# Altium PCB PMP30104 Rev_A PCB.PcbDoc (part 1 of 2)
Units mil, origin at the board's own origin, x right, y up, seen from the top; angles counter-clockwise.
Board outline 1835 x 2150 mil, 2 copper layers (Top Layer, Bottom Layer), stack 62 mil thick; 81 components, 42 nets, 182 pads, 76 vias.
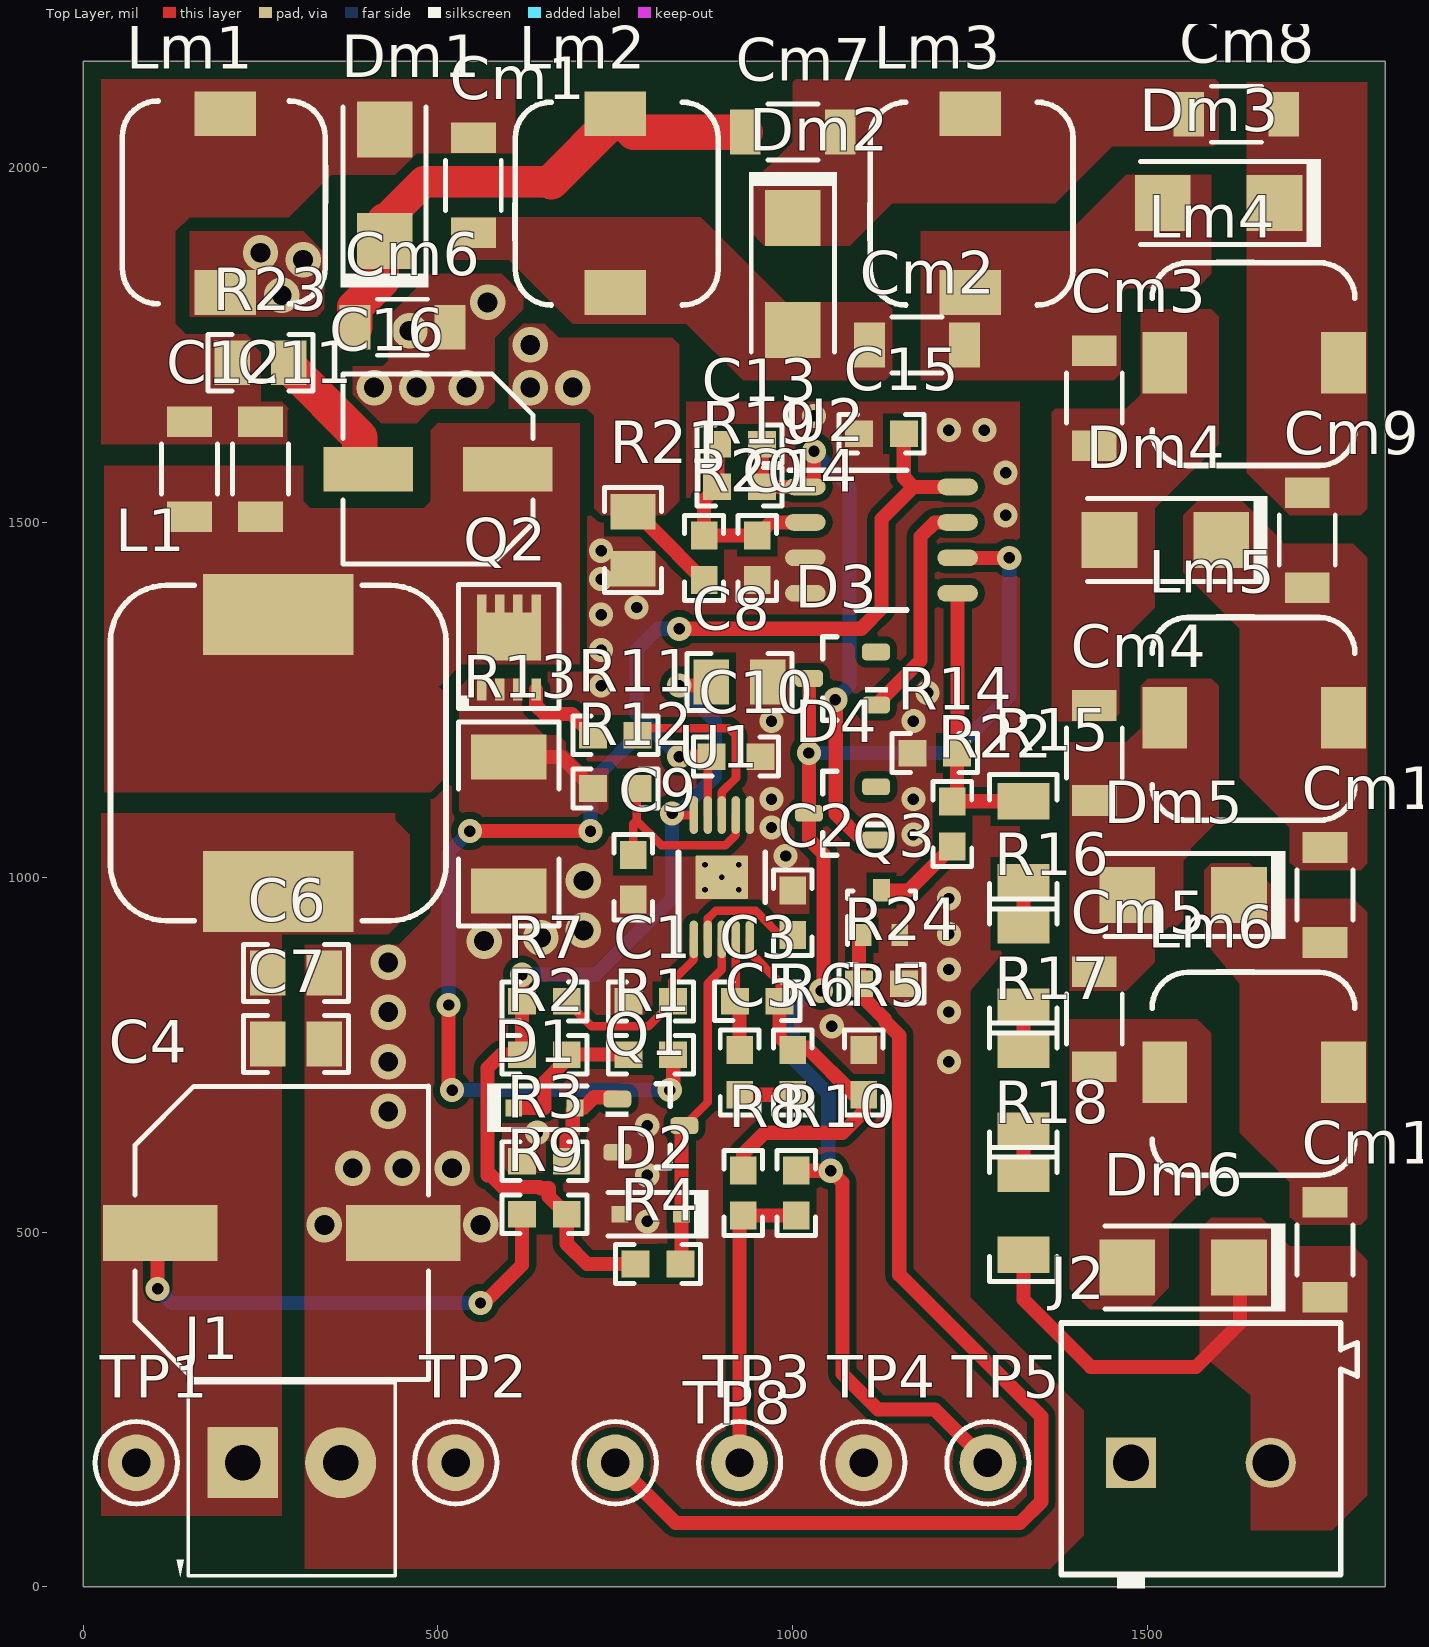
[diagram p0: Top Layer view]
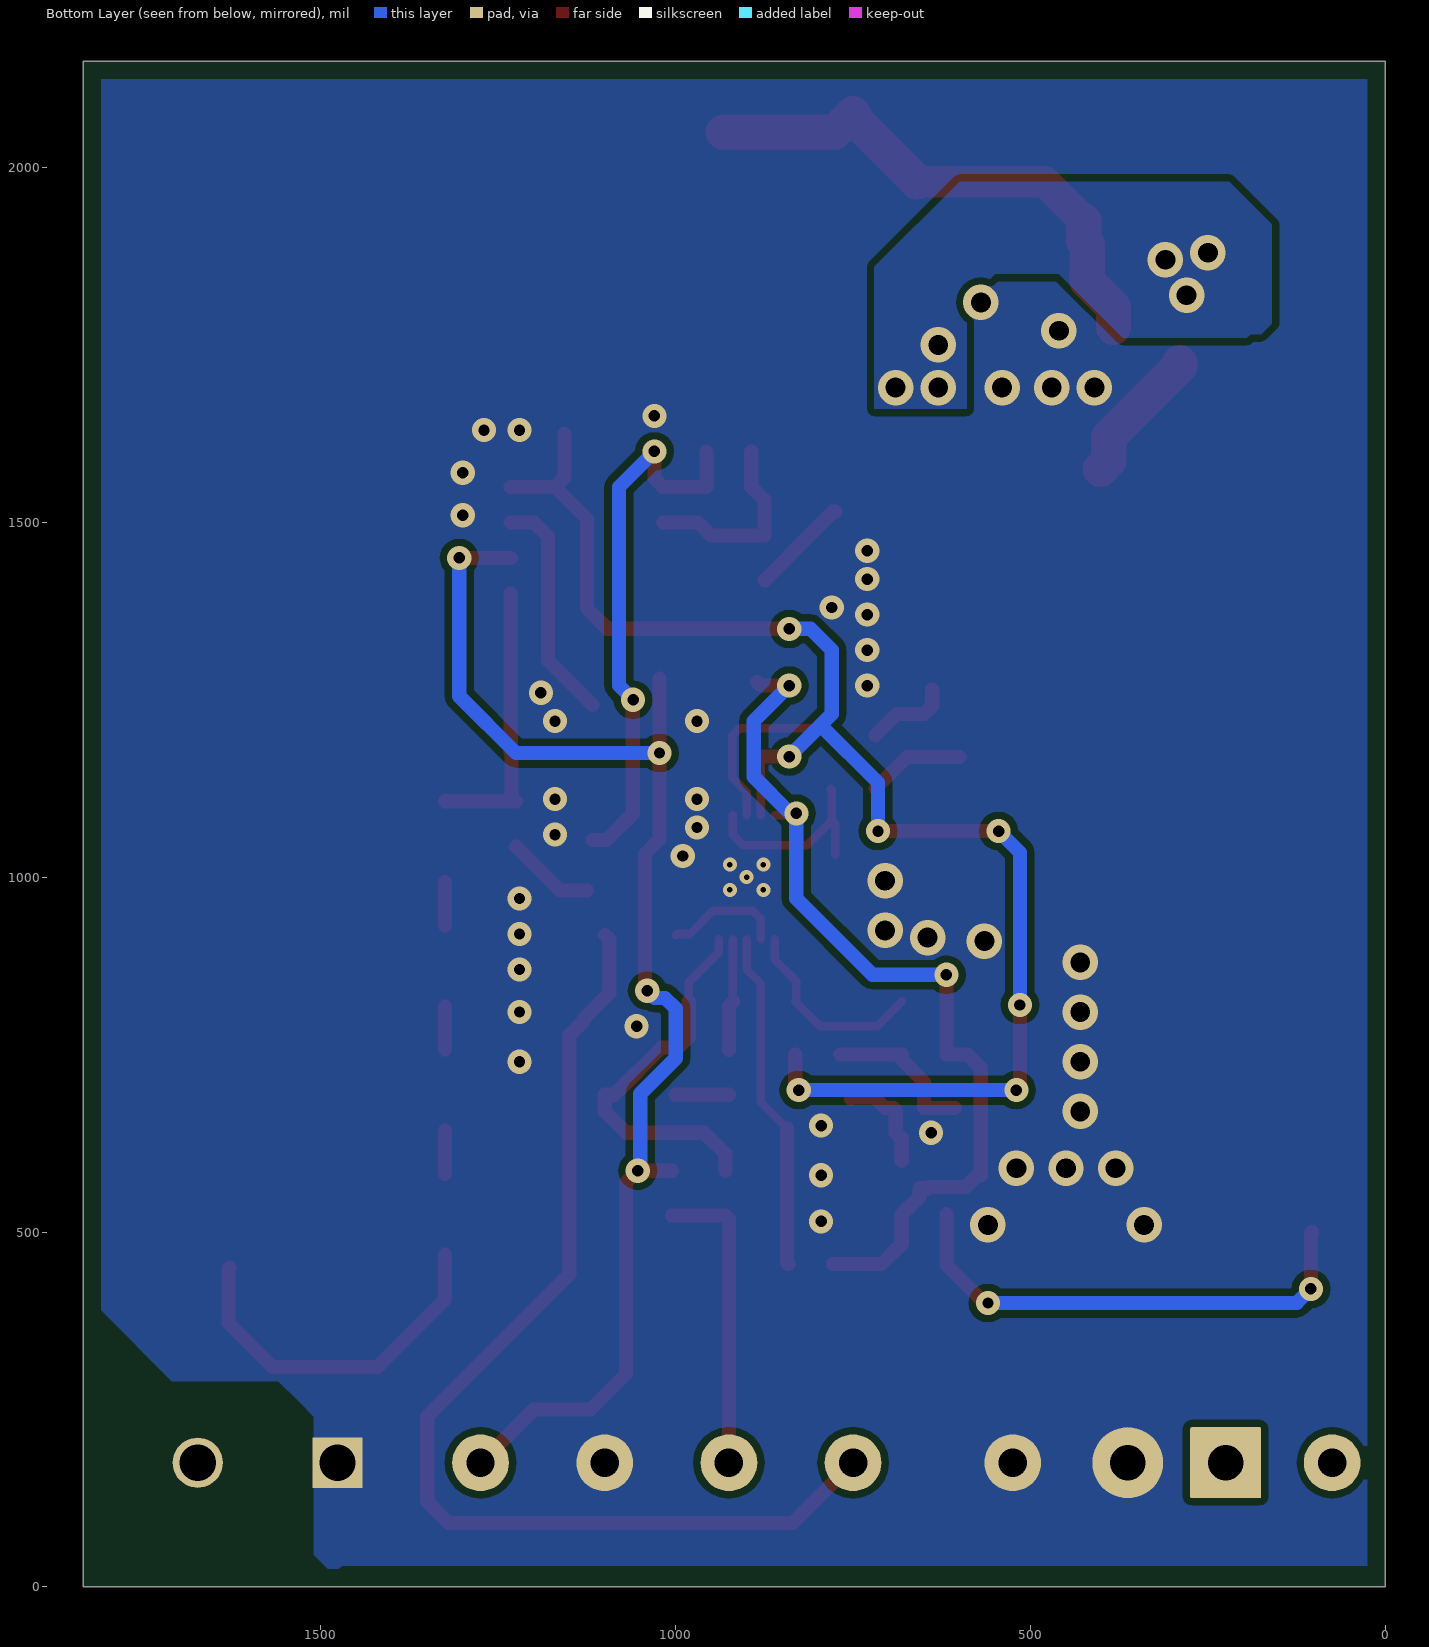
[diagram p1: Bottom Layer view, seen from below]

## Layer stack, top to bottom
Top Solder: solder mask 0.4, Solder Resist, Dk 3.5
Top Layer: signal copper 1.4
Dielectric1: core 59.2, FR-4, Dk 4.8
Bottom Layer: signal copper 1.4
Bottom Solder: solder mask 0.4, Solder Resist, Dk 3.5

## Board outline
0,0 0,2150 1835,2150 1835,0

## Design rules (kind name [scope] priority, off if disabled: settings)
AcuteAngle [All] p1: minimum=4.50000000000000E+0001 checktracksonly=FALSE
AssemblyTestPointUsage [All] p1: valid=2
BoardOutlineClearance BoardOutlineClearance_MountingHoles [OnCopper and InComponentClass('Mounting Holes')] p1: gap=40
BoardOutlineClearance BoardOutlineClearance_Poly [OnCopper and IsPoly] p2: gap=25
BoardOutlineClearance [OnCopper and Not InComponentClass('Logo') and not InComponentClass('FiducialMark') and not InRegion(1000,500,4000,800) and not InPoly] p3: gap=75
Clearance Clearance_Keepouts [((IsTrack Or IsArc) And Not InPoly) And IsFree and IsKeepOut vs ((IsTrack Or IsArc) And Not InPoly) And IsFree and IsKeepOut] p1: gap=0
Clearance Clearance_Poly [InPolygon] p2: gap=10
Clearance [All] p3: gap=8
ComponentClearance ComponentClearance_MountingHoles_FiducialMarks [InComponentClass('Mounting Holes') vs InComponentClass('FiducialMark')] p1: gap=50 collisioncheckmode=3 verticalgap=10 showdistances=FALSE
ComponentClearance ComponentClearance_Shunt [InComponentClass('Header') vs InComponentClass('Shunt')] p2: gap=0 collisioncheckmode=3 verticalgap=0 showdistances=FALSE
ComponentClearance ComponentClearance_Logo [InComponentClass('Logo')] p3: gap=50 collisioncheckmode=3 verticalgap=10 showdistances=FALSE
ComponentClearance ComponentClearance_ScrewToNut [(HasFootprint('NY PMS 440 0025 PH')) vs (HasFootprint('Keystone_1902C'))] p4: gap=5 collisioncheckmode=3 verticalgap=10 showdistances=FALSE
ComponentClearance ComponentClearance_MountingHoles [InComponentClass('Mounting Holes')] p5: gap=250 collisioncheckmode=3 verticalgap=100000 showdistances=FALSE
ComponentClearance ComponentClearance_SmallPassives [HasFootprint('0201*') or HasFootprint('0402*') or HasFootprint('0508') or HasFootprint('0603*') or HasFootprint('0612') or HasFootprint('0805*') or HasFootprint('0815*') or HasFootprint('0830*') or HasFootprint('1206*') or HasFootprint('1210*') or HasFootprint('1808*') or HasFootprint('1812*') or HasFootprint('1825*') or HasFootprint('2010*') or HasFootprint('2220*') or HasFootprint('2225*') or HasFootprint('2512*') or HasFootprint('2728*') or HasFootprint('3518*') vs HasFootprint('0201*') or HasFootprint('0402*') or HasFootprint('0508') or HasFootprint('0603*') or HasFootprint('0612') or HasFootprint('0805*') or HasFootprint('0815*') or HasFootprint('0830*') or HasFootprint('1206*') or HasFootprint('1210*') or HasFootprint('1808*') or HasFootprint('1812*') or HasFootprint('1825*') or HasFootprint('2010*') or HasFootprint('2220*') or HasFootprint('2225*') or HasFootprint('2512*') or HasFootprint('2728*') or HasFootprint('3518*')] p6: gap=10 collisioncheckmode=3 verticalgap=10 showdistances=FALSE
ComponentClearance ComponentClearance_THtoSMT [IsThruComponent vs IsSMTComponent] p7: gap=10 collisioncheckmode=3 verticalgap=10 showdistances=FALSE
ComponentClearance ComponentClearance_THtoTH [IsThruComponent vs IsThruComponent] p8: gap=10 collisioncheckmode=3 verticalgap=10 showdistances=FALSE
ComponentClearance [All] p9: gap=10 collisioncheckmode=3 verticalgap=10 showdistances=FALSE
DiffPairsRouting [All] p1: maxlimit=100 minlimit=10 mostfreqgap=10 toplayer_minwidth=15 toplayer_maxwidth=15 toplayer_prefwidth=15 bottomlayer_minwidth=15 bottomlayer_maxwidth=15 bottomlayer_prefwidth=15 maxuncoupledlength=1000
FabricationTestPointUsage TestPointUsage [All] p1: valid=2 allowmultiple=FALSE
FabricationTestpoint Testpoint [All] p1: side=3 testpointundercomponent=TRUE minsize=40 maxsize=100 preferedsize=60 minholesize=0 maxholesize=40 preferedholesize=32 testpointgrid=1 allowsidetop=TRUE allowsidebottom=TRUE usegrid=TRUE gridtolerance=0.01
FanoutControl Fanout_LCC [IsLCC] p1: bgadir=Out bgaviamode=Centered fanoutstyle=Auto fanoutdirection=Alternating viagrid=1 // Fanout_LCC (Default Rule)
FanoutControl Fanout_BGA [IsBGA] p2: bgadir=Out bgaviamode=Centered fanoutstyle=Auto fanoutdirection=Alternating viagrid=1 // Fanout_BGA (Default Rule)
FanoutControl Fanout_Default [All] p4: bgadir=Out bgaviamode=Centered fanoutstyle=Auto fanoutdirection=Alternating viagrid=1 // Fanout_Default (Default Rule)
FanoutControl Fanout_Small [(CompPinCount < 5)] p5: bgadir=Out bgaviamode=Centered fanoutstyle=Auto fanoutdirection=OutThenIn viagrid=1 // Fanout_Small (Default Rule)
HoleSize [All] p1: absolutevalues=TRUE maxlimit=251 minlimit=7.87 maxpercent=80.000 minpercent=20.000
MinimumAnnularRing MinimumAnnularRing_ThermalPadVias [IsVia and InAnyComponent] p1: minimumring=5.91
MinimumAnnularRing [All] p2: minimumring=8
MinimumSolderMaskSliver MinimumSolderMaskSliver_Logo [InComponentClass('Logo') vs InComponentClass('Logo')] p1: minsoldermaskwidth=0.7
MinimumSolderMaskSliver [All] p2: minsoldermaskwidth=3.94
PlaneConnect [All] p1: planeconnectstyle=Relief reliefexpansion=10 reliefentries=4 reliefconductorwidth=10 reliefairgap=10
PolygonConnect PolygonConnect_21 [All vs IsNamedPolygon('Bottom Layer-No Net 1')] p1: connectstyle=Direct reliefconductorwidth=10 reliefentries=4 polygonreliefangle="90 Angle" airgapwidth=10
PolygonConnect PolygonConnect_20 [All vs IsNamedPolygon('Top Layer-No Net 16')] p2: connectstyle=Direct reliefconductorwidth=10 reliefentries=4 polygonreliefangle="90 Angle" airgapwidth=10
PolygonConnect PolygonConnect_19 [All vs IsNamedPolygon('Top Layer-No Net 15')] p3: connectstyle=Direct reliefconductorwidth=10 reliefentries=4 polygonreliefangle="90 Angle" airgapwidth=10
PolygonConnect PolygonConnect_18 [All vs IsNamedPolygon('Bottom Layer-No Net')] p4: connectstyle=Direct reliefconductorwidth=10 reliefentries=4 polygonreliefangle="90 Angle" airgapwidth=10
PolygonConnect PolygonConnect_17 [All vs IsNamedPolygon('Top Layer-No Net 14')] p5: connectstyle=Direct reliefconductorwidth=10 reliefentries=4 polygonreliefangle="90 Angle" airgapwidth=10
PolygonConnect PolygonConnect_16 [All vs IsNamedPolygon('Top Layer-No Net 13')] p6: connectstyle=Direct reliefconductorwidth=10 reliefentries=4 polygonreliefangle="90 Angle" airgapwidth=10
PolygonConnect PolygonConnect_15 [All vs IsNamedPolygon('Top Layer-No Net 12')] p7: connectstyle=Direct reliefconductorwidth=10 reliefentries=4 polygonreliefangle="90 Angle" airgapwidth=10
PolygonConnect PolygonConnect_14 [All vs IsNamedPolygon('Top Layer-No Net 11')] p8: connectstyle=Direct reliefconductorwidth=10 reliefentries=4 polygonreliefangle="90 Angle" airgapwidth=10
PolygonConnect PolygonConnect_13 [All vs IsNamedPolygon('Top Layer-No Net 10')] p9: connectstyle=Direct reliefconductorwidth=10 reliefentries=4 polygonreliefangle="90 Angle" airgapwidth=10
PolygonConnect PolygonConnect_12 [All vs IsNamedPolygon('Top Layer-No Net 9')] p10: connectstyle=Direct reliefconductorwidth=10 reliefentries=4 polygonreliefangle="90 Angle" airgapwidth=10
PolygonConnect PolygonConnect_11 [All vs IsNamedPolygon('Top Layer-No Net 9')] p11: connectstyle=Direct reliefconductorwidth=10 reliefentries=4 polygonreliefangle="90 Angle" airgapwidth=10
PolygonConnect PolygonConnect_10 [All vs IsNamedPolygon('Top Layer-No Net 8')] p12: connectstyle=Direct reliefconductorwidth=10 reliefentries=4 polygonreliefangle="90 Angle" airgapwidth=10
PolygonConnect PolygonConnect_9 [All vs IsNamedPolygon('Top Layer-No Net 7')] p13: connectstyle=Direct reliefconductorwidth=10 reliefentries=4 polygonreliefangle="90 Angle" airgapwidth=10
PolygonConnect PolygonConnect_8 [All vs IsNamedPolygon('Top Layer-No Net 6')] p14: connectstyle=Direct reliefconductorwidth=10 reliefentries=4 polygonreliefangle="90 Angle" airgapwidth=10
PolygonConnect PolygonConnect_7 [All vs IsNamedPolygon('Top Layer-No Net 5')] p15: connectstyle=Direct reliefconductorwidth=10 reliefentries=4 polygonreliefangle="90 Angle" airgapwidth=10
PolygonConnect PolygonConnect_6 [All vs IsNamedPolygon('Top Layer-No Net 4')] p16: connectstyle=Direct reliefconductorwidth=10 reliefentries=4 polygonreliefangle="90 Angle" airgapwidth=10
PolygonConnect PolygonConnect_5 [All vs IsNamedPolygon('Top Layer-No Net')] p17: connectstyle=Direct reliefconductorwidth=10 reliefentries=4 polygonreliefangle="90 Angle" airgapwidth=10
PolygonConnect PolygonConnect_4 [All vs IsNamedPolygon('Top Layer-No Net 3')] p18: connectstyle=Direct reliefconductorwidth=10 reliefentries=4 polygonreliefangle="90 Angle" airgapwidth=10
PolygonConnect PolygonConnect_3 [All vs IsNamedPolygon('Top Layer-No Net 2')] p19: connectstyle=Direct reliefconductorwidth=10 reliefentries=4 polygonreliefangle="90 Angle" airgapwidth=10
PolygonConnect PolygonConnect_2 [All vs IsNamedPolygon('Top Layer-No Net 1')] p20: connectstyle=Direct reliefconductorwidth=10 reliefentries=4 polygonreliefangle="90 Angle" airgapwidth=10
PolygonConnect PolygonConnect_1 [All vs IsNamedPolygon('Top Layer-No Net')] p21: connectstyle=Direct reliefconductorwidth=10 reliefentries=4 polygonreliefangle="90 Angle" airgapwidth=10
PolygonConnect [All] p22: connectstyle=Relief reliefconductorwidth=10 reliefentries=4 polygonreliefangle="90 Angle" airgapwidth=10
RoutingVias ThermalPadVias [IsVia and InAnyComponent] p1: holewidth=7.87 width=19.68 viastyle="Through Hole" minholewidth=7.87 minwidth=19.68 maxholewidth=12.99 maxwidth=23.62
RoutingVias [All] p2: holewidth=16 width=34 viastyle="Through Hole" minholewidth=7.87 minwidth=26 maxholewidth=40 maxwidth=65
SilkToBoardRegionClearance [Not ((IsComment or IsDesignator) And (Hide <> 'False')) and not InRegion(1000,500,4000,800)] p1:
SilkToSilkClearance SilkToSilkClearance_Pb-FreeLogo [(HasFootprint('Pb-Free_Overlay_Medium') OR HasFootprint('Pb-Free_Overlay_Small')) vs (HasFootprint('Pb-Free_Overlay_Medium') OR HasFootprint('Pb-Free_Overlay_Small'))] p1: silktosilkclearance=0
SilkToSilkClearance [All] p2: silktosilkclearance=4
SilkToSolderMaskClearance SilkToComponentPadClearance [IsPad and InAnycomponent] p1: minsilkscreentomaskgap=5 clearancetoexposedcopper=TRUE
SilkToSolderMaskClearance "Silk to Solder Mask Opening" [All] p2: minsilkscreentomaskgap=4 clearancetoexposedcopper=FALSE
SolderMaskExpansion [All] p1: expansion=1.97
Width [All] p1: maxlimit=100 minlimit=6 preferedwidth=10 checkconnectedcopper=TRUE
15 further rules are at their usual default settings.

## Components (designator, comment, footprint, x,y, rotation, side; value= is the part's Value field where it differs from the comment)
C1 "GRM188R71H331KA01D" 0603#1 800,825 r180 top
C2 "GRM188R71E224KA88D" 0603#1 1000,950 r90 top
C3 "GRM188R71H102KA01D" 0603#1 950,825 r0 top
C4 "EEE-FC1E221P" SM_RADIAL_G 280,498.74 r0 top
C5 "GRM188R71H104KA93D" 0603#1 925,725 r270 top
C6 "C2012X5R1E106K125AB" 0805_HV 300,865 r0 top
C7 "C2012X5R1E106K125AB" 0805_HV 300,765 r0 top
C8 "GRM21BR71H105KA12L" 0805_HV 925,1275 r0 top
C9 "06033C101KAT2A" 0603#1 775,1000 r270 top
C10 "GRM188R71E105KA12D" 0603#2 920,1170 r0 top
C11 "C3216X5R1H106K160AB" 1206_180 250,1575 r270 top
C12 "C3216X5R1H106K160AB" 1206_180 150,1575 r270 top
C13 "GRM188R71H102KA01D" 0603#1 925,1610 r0 top
C14 "GRM188R71H103KA01D" 0603#1 950,1450 r90 top
C15 "GCM188R71H104KA57D" 0603#1 1125,1625 r0 top
C16 "EEE-FK1E101XP" SM_RADIAL_D8 500,1575 r180 top
Cm1 "GRM31CR72A225KA73K" 1206_190 550,1975 r270 top
Cm2 "GRM31CR72A225KA73K" 1206_190 1175,1750 r0 top
Cm3 "GRM31CR72A225KA73K" 1206_190 1425,1675 r270 top
Cm4 "GRM31CR72A225KA73K" 1206_190 1425,1175 r270 top
Cm5 "GRM31CR72A225KA73K" 1206_190 1425,800 r270 top
Cm6 "GRM31CR72A225KA73K" 1206_190 450,1775 r180 top
Cm7 "GRM31CR72A225KA73K" 1206_190 1000,2050 r0 top
Cm8 "GRM31CR72A225KA73K" 1206_190 1625,2075 r0 top
Cm9 "GRM31CR72A225KA73K" 1206_190 1725,1475 r270 top
Cm10 "GRM31CR72A225KA73K" 1206_190 1750,975 r270 top
Cm11 "GRM31CR72A225KA73K" 1206_190 1750,475 r270 top
D1 "MMSZ5235BS-7-F" sod-323 650,675 r0 top
D2 "MMSZ5235BS-7-F" sod-323 800,525 r180 top
D3 "BAS16-7-F" SOT-23 1070,1280 r180 top
D4 "BAS16-7-F" SOT-23 1070,1090 r180 top
Dm1 "STPS1150A" SMA 425,1975 r90 top
Dm2 "STPS1150A" SMA 1000,1850 r270 top
Dm3 "STPS1150A" SMA 1600,1950 r180 top
Dm4 "STPS1150A" SMA 1525,1475 r180 top
Dm5 "STPS1150A" SMA 1550,975 r180 top
Dm6 "STPS1150A" SMA 1550,450 r180 top
J1 "ED555/2DS" TERM_BLK_ED555-2DS 225,175 r0 top
J2 "691 101 710 002" Wurth_691101710002 1575,175 r0 top
L1 "7447709470" WE-PD_1210 275,1175 r90 top
Lm1 "74477730" WE-PD_7345 200,1950 r270 top
Lm2 "74477730" WE-PD_7345 750,1950 r90 top
Lm3 "74477730" WE-PD_7345 1250,1950 r90 top
Lm4 "74477730" WE-PD_7345 1650,1725 r0 top
Lm5 "74477730" WE-PD_7345 1650,1225 r0 top
Lm6 "74477730" WE-PD_7345 1650,725 r0 top
Q1 "MMBT2222A" SOT-23 800,650 r0 top
Q2 "BSZ520N15NS3 G" PG-TSDSON-8 600,1325 r90 top
Q3 "BSS138W-7-F" SOT-323 1125,950 r90 top
R1 "CRCW0603100KFKEA" 0603#1 800,750 r0 top
R2 "CRCW060320K0FKEA" 0603#1 650,750 r180 top
R3 "CRCW0603100KFKEA" 0603#1 650,600 r0 top
R4 "CRCW060320K0FKEA" 0603#1 810,455 r180 top
R5 "CRCW06033K92FKEA" 0603#1 1100,725 r270 top
R6 "CRCW060310K0FKEA" 0603#1 1000,725 r90 top
R7 "RC0603FR-07261KL" 0603#1 650,825 r180 top
R8 "CRCW060310K0FKEA" 0603#1 930,555 r270 top
R9 "CRCW06034R64FKEA" 0603#1 650,525 r180 top
R10 "CRCW060349R9FKEA" 0603#1 1005,555 r90 top
R11 "RC0603FR-072R21L" 0603#1 750,1200 r180 top
R12 "CRCW06031K00FKEA" 0603#1 750,1125 r180 top
R13 "CSRN2010FK25L0" 2010M 600,1075 r90 top
R14 "RC0603FR-0725K5L" 0603#1 1200,1175 r0 top
R15 "RC1206FR-071ML" 1206 1325,1050 r90 top
R16 "RC1206FR-071ML" 1206 1325,875 r90 top
R17 "RC1206FR-071ML" 1206 1325,700 r90 top
R18 "RC1206FR-071ML" 1206 1325,525 r90 top
R19 "RC0603FR-0724K9L" 0603#1 925,1550 r0 top
R20 "CRCW06031K00FKEA" 0603#1 875,1450 r90 top
R21 "ERJ-6RQF1R0V" 0805_HV 775,1475 r270 top
R22 "RC0603FR-07392KL" 0603#1 1225,1075 r90 top
R23 "RC0805FR-0710RL" 0805_HV 250,1725 r180 top
R24 "CRCW060310K0FKEA" 0603#1 1125,850 r0 top
TP1 "5000" Keystone5000 75,175 r0 top
TP2 "5001" Keystone5001 525,175 r0 top
TP3 "5003" Keystone5003 925,175 r0 top
TP4 "5001" Keystone5001 1100,175 r0 top
TP5 "5000" Keystone5000 1275,175 r90 top
TP8 "5000" Keystone5000 750,175 r90 top
U1 "TPS40210DGQR" DGQ0010D_N 900,1000 r90 top
U2 "TLC272CD" D0008A_N 1125,1475 r0 top

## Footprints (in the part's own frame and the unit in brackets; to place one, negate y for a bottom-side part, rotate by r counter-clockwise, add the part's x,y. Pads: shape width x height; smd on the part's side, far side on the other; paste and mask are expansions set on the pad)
0603#1 [mm] "0603 from SM-752 data"
  rect 1x0.95 smd: 1(-0.8,0) 2(0.8,0)
  silkscreen extent -1.52,-0.69 1.52,0.69, body extent -0.87,-0.47 0.87,0.47, height 1
0603#2 [mm] "0603 from SM-752 data"
  rect 1x0.95 smd: 1(-0.876,0) 2(0.876,0)
  silkscreen extent -1.52,-0.69 1.52,0.69, body extent -0.87,-0.47 0.87,0.47, height 1
0805_HV [mil] "0805 with 30mil clearance between pads"
  rect 50x63 smd: 1(-40,0) 2(40,0)
  silkscreen extent -74,-40 74,40, body extent -43,-29 43,29, height 57
1206 [mm] "1206 from SM-752 data"
  rect 1.3x1.85 smd: 1(-1.45,0) 2(1.45,0)
  silkscreen extent -2.4,-1.21 2.4,1.21, body extent -1.7,-0.9 1.7,0.9, height 1.35
1206_180 [mm] "1206_180"
  rect 1.1x1.6 smd: 1(-1.7,0) 2(1.7,0)
  silkscreen extent -0.9,-1 0.9,1, body extent -1.75,-0.95 1.75,0.95, height 1.8
1206_190 [mm] "1206_190"
  rect 1.1x1.6 smd: 1(-1.7,0) 2(1.7,0)
  silkscreen extent -0.9,-1 0.9,1, body extent -1.75,-0.95 1.75,0.95, height 1.9
2010M [mm]
  rect 1.6x2.7 smd: 1(-2.4,0) 2(2.4,0)
  silkscreen extent -3.65,-1.8 3.65,1.8, body extent -2.73,-1.45 2.73,1.45, height 1.66
D0008A_N [mm] "SOIC, 8-Leads, Body 4.9x3.9mm, Pitch 1.27mm, IPC Medium Density"
  oval 1.45x0.6 smd: 1(-2.725,1.905) 2(-2.725,0.635) 3(-2.725,-0.635) 4(-2.725,-1.905) 5(2.725,-1.905) 6(2.725,-0.635) 7(2.725,0.635) 8(2.725,1.905)
  silkscreen extent -3.3,-2.5 0.9,2.5, body extent -3,-2.45 3,2.45, height 1.63
DGQ0010D_N [mm] "TSSOP, 10-Leads, Body 3x3mm, Pitch 0.5mm, Thermal Pad 1.88x1.57mm, IPC Medium Density"
  rrect100% 1.35x0.3 smd: 1(-2.225,1) 2(-2.225,0.5) 3(-2.225,0) 4(-2.225,-0.5) 5(-2.225,-1) 6(2.225,-1) 7(2.225,-0.5) 8(2.225,0) 9(2.225,0.5) 10(2.225,1)
  rrect6% 1.57x1.88 smd: 11(0,0)
  silkscreen extent -2.65,-1.55 0.9,1.55, body extent -2.46,-1.5 2.46,1.5, height 1.1
Keystone5000 [mil] "For Keystone 500x miniature loop terminals"
  round 80 hole 40: 1(0,0)
  silkscreen extent -58,-58 58,58, body extent -49,-49 49,49, height 182
Keystone5001 [mil] "For Keystone 500x miniature loop terminals"
  round 80 hole 40: 1(0,0)
  silkscreen extent -58,-58 58,58, body extent -49,-49 49,49, height 182
Keystone5003 [mil] "For Keystone 500x miniature loop terminals"
  round 80 hole 40: 1(0,0)
  silkscreen extent -58,-58 58,58, body extent -49,-49 49,49, height 182
PG-TSDSON-8 [mm] "Infineon recommended land pattern"
  rect 0.8x0.34 smd: 1(-1.538,0.975) 2(-1.538,0.325) 3(-1.538,-0.325) 4(-1.538,-0.975)
  rect 0.65x0.34 smd: 5(1.538,-0.975) 6(1.538,-0.325) 7(1.538,0.325) 8(1.538,0.975)
  rect 1.71x2.29 smd: 9(0.358,0)
  silkscreen extent -2.22,-1.8 2.22,1.8, body extent -1.7,-1.7 1.7,1.7, height 1.1
SM_RADIAL_D8 [mm] "6.3 x 7.7mm:  Panasonic D8"
  rect 3.2x1.6 smd: 1(-2.5,0) 2(2.5,0)
  silkscreen extent -3.4,-3.4 3.4,3.4, body extent -3.4,-3.4 3.4,3.4, height 8.01
SM_RADIAL_G [mm] "10 x 10.2mm:  Panasonic G"
  rect 4.1x2 smd: 1(-4.35,0) 2(4.35,0)
  silkscreen extent -5.25,-5.25 5.25,5.25, body extent -5.25,-5.25 5.25,5.25, height 10.5
SMA [mm] "Molded Diode, 2-Leads, Body 4.3x2.6mm, IPC Medium Density, based on OnSemi component dimensions and land pattern"
  rect 2x2 smd: 1(-2,0) 2(2,0)
  silkscreen extent -3.66,-1.57 2.79,1.57, body extent -2.6,-1.3 2.6,1.3, height 2.42
sod-323 [mm] "NXP recommended land pattern"
  rect 0.6x0.6 smd paste-0.05: 1(-1.1,0) 2(1.1,0)
  silkscreen extent -2.06,-0.86 1.53,0.86, body extent -1.3,-0.67 1.3,0.68, height 1.1
SOT-23 [mm] "SOT23, 3-Leads, Body 2.9x1.3mm, Pitch 0.95mm, Lead Span 2.5mm, IPC Medium Density"
  rrect50% 1x0.6 smd: 1(-1.2,0.95) 2(-1.2,-0.95) 3(1.2,0)
  silkscreen extent -1.63,-1.5 0.7,1.5, body extent -1.16,-1.45 1.21,1.45, height 1
SOT-323 [mm] "Zetex recommended land pattern.  March 2007"
  rect 0.8x0.6 smd: 1(-0.8,0.65) 2(-0.8,-0.65) 3(0.8,0)
  silkscreen extent -1.14,-1.22 0.77,1.22, body extent -1.13,-1.13 1.12,1.12, height 1.13
TERM_BLK_ED555-2DS [mil]
  rrect4% 100x100 hole 50: 1(0,0)
  round 100 hole 50: 2(138,0)
  silkscreen extent -93,-161 215,113, body extent -69,-150 207,106, height 323
WE-PD_1210 [mm] "Wurth Elektronik recommended land pattern"
  rect 2.9x5.4 smd: 1(-4.95,0) 2(4.95,0)
  silkscreen extent -6,-6 6,6, body extent -6,-6 6,6, height 10.01
WE-PD_7345 [mm] "SMD Inductor, 2-Leads, Body 7,3x7,3mm"
  rect 1.6x2.2 smd: 1(-3.2,0) 2(3.2,0)
  silkscreen extent -3.65,-3.68 3.61,3.6, body extent -3.65,-3.68 3.65,3.6, height 4.49
Wurth_691101710002 [mm] "Terminal Block, 5 mm, 2x1, TH"
  rect 1.8x1.8 hole 1.3: 1(-2.5,0)
  round 1.8 hole 1.3: 2(2.5,0)
  silkscreen extent -5,-4.5 5.6,5, body extent -5.6,-4 5.6,5, height 12.5

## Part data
C1: "CAP, CERM, 330pF, 50V, +/-10%, X7R, 0603"
C2: "CAP, CERM, 0.22uF, 25V, +/-10%, X7R, 0603"
C3 C13: "CAP, CERM, 1000pF, 50V, +/-10%, X7R, 0603"
C4: "CAP, AL, 220 µF, 25 V, +/- 20%, 0.15 ohm, SMD"
C5: "CAP, CERM, 0.1 µF, 50 V, +/- 10%, X7R, 0603"
C6 C7: "CAP, CERM, 10 µF, 25 V, +/- 10%, X5R, 0805"
C8: "CAP, CERM, 1uF, 50V, +/-10%, X7R, 0805"
C9: "CAP, CERM, 100pF, 25V, +/-10%, X7R, 0603"
C10: "CAP, CERM, 1uF, 25V, +/-10%, X7R, 0603"
C11 C12: "CAP, CERM, 10 µF, 50 V, +/- 10%, X5R, 1206"
C14: "CAP, CERM, 0.01uF, 50V, +/-10%, X7R, 0603"
C15: "CAP, CERM, 0.1uF, 50V, +/-10%, X7R, 0603"
C16: "CAP, AL, 100 µF, 25 V, +/- 20%, 0.34 ohm, SMD"
Cm1 Cm2 Cm3 Cm4 Cm5 Cm6 Cm7 Cm8 Cm9 Cm10 Cm11: library part GRM31CR72A225KA73L, "CAP, CERM, 2.2 µF, 100 V, +/- 10%, X7R, 1206_190"
D1 D2: "Diode, Zener, 6.8V, 200mW, SOD-323"
D3 D4: "Diode, Ultrafast, 75V, 0.3A, SOT-23"
Dm1 Dm2 Dm3 Dm4 Dm5 Dm6: "Diode, Schottky, 150 V, 1 A, SMA"
J1: "Terminal Block, 6A, 3.5mm Pitch, 2-Pos, TH"
J2: "Terminal Block, 5 mm, 2x1, Tin, TH"
L1: "Inductor, Shielded Drum Core, Ferrite, 47 µH, 3.8 A, 0.04593 ohm, SMD"
Lm1 Lm2 Lm3 Lm4 Lm5 Lm6: "Inductor, Shielded Drum Core, Metal Composite, 1 mH, 0.2 A, 3.27 ohm, SMD"
Q1: library part "MMBT2222A, Fairchild Semiconductor", "Transistor, NPN, 40V, 0.15A, SOT-23"
Q2: "MOSFET, N-CH, 150 V, 21 A, PG-TSDSON-8"
Q3: "MOSFET, N-CH, 50 V, 0.2 A, SOT-323"
R1 R3: "RES, 100k ohm, 1%, 0.1W, 0603"
R2 R4: "RES, 20.0k ohm, 1%, 0.1W, 0603"
R5: "RES, 3.92k ohm, 1%, 0.1W, 0603"
R6 R8 R24: "RES, 10.0k ohm, 1%, 0.1W, 0603"
R7: "RES, 261 k, 1%, 0.1 W, 0603"
R9: "RES, 4.64 ohm, 1%, 0.1W, 0603"
R10: "RES, 49.9 ohm, 1%, 0.1W, 0603"
R11: "RES, 2.21, 1%, 0.1 W, 0603"
R12: "RES, 1.00k ohm, 1%, 0.1W, 0603"
R13: "RES, 0.025 ohm, 1%, 1W, 2010"
R14: "RES, 25.5 k, 1%, 0.1 W, 0603"
R15 R16 R17 R18: "RES, 1.00 M, 1%, 0.25 W, 1206"
R19: "RES, 24.9 k, 1%, 0.1 W, 0603"
R20: "RES, 1.00 k, 1%, 0.1 W, 0603"
R21: "RES, 1.00, 1%, 0.125 W, 0805"
R22: "RES, 392 k, 1%, 0.1 W, 0603"
R23: "RES, 10.0, 1%, 0.125 W, 0805"
TP1 TP5 TP8: "Test Point, Miniature, Red, TH"
TP2 TP4: "Test Point, Miniature, Black, TH"
TP3: "Test Point, Miniature, Orange, TH"
U1: "4.5-V TO 52-V INPUT CURRENT MODE BOOST CONTROLLER, DGQ0010D"
U2: "IC, Precision Dual Operational Amplifiers"

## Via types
v1: diameter 34, hole 16, Top Layer to Bottom Layer, 47 vias
v2: diameter 50, hole 28, Top Layer to Bottom Layer, 24 vias
v3: diameter 19.68, hole 7.87, Top Layer to Bottom Layer, 5 vias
